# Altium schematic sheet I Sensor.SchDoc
size 431 x 279 mm; Date: Not shown in title block; ApprovedBy: Not shown in title block; CheckedBy: Not shown in title block; Author: Not shown in title block; CompanyName: Not shown in title block; DrawnBy: Forest Fu; Engineer: Not shown in title block; Organization: Not shown in title block; Address1: Not shown in title block; Address2: Not shown in title block; Address3: Not shown in title block; Address4: Not shown in title block; DocumentNumber: 1; Revision: Use project parameter SCH_Rev; SheetNumber: 5; SheetTotal: 6; PageSetup: Record=PageOptions¦CenterHorizontal=True¦CenterVertical=True¦PrintScale=1.00¦XCorrection=1.00¦YCorrection=1.00¦PrintKind=0¦BorderSize=5000000¦LeftOffset=0¦BottomOffset=0¦Orientation=2¦PaperLength=1000¦PaperWidth=1000¦Scale=100¦PaperSource=15¦PrintQuality=600¦MediaType=1¦DitherType=10¦PaperKind=Letter¦PrintScaleMode=1
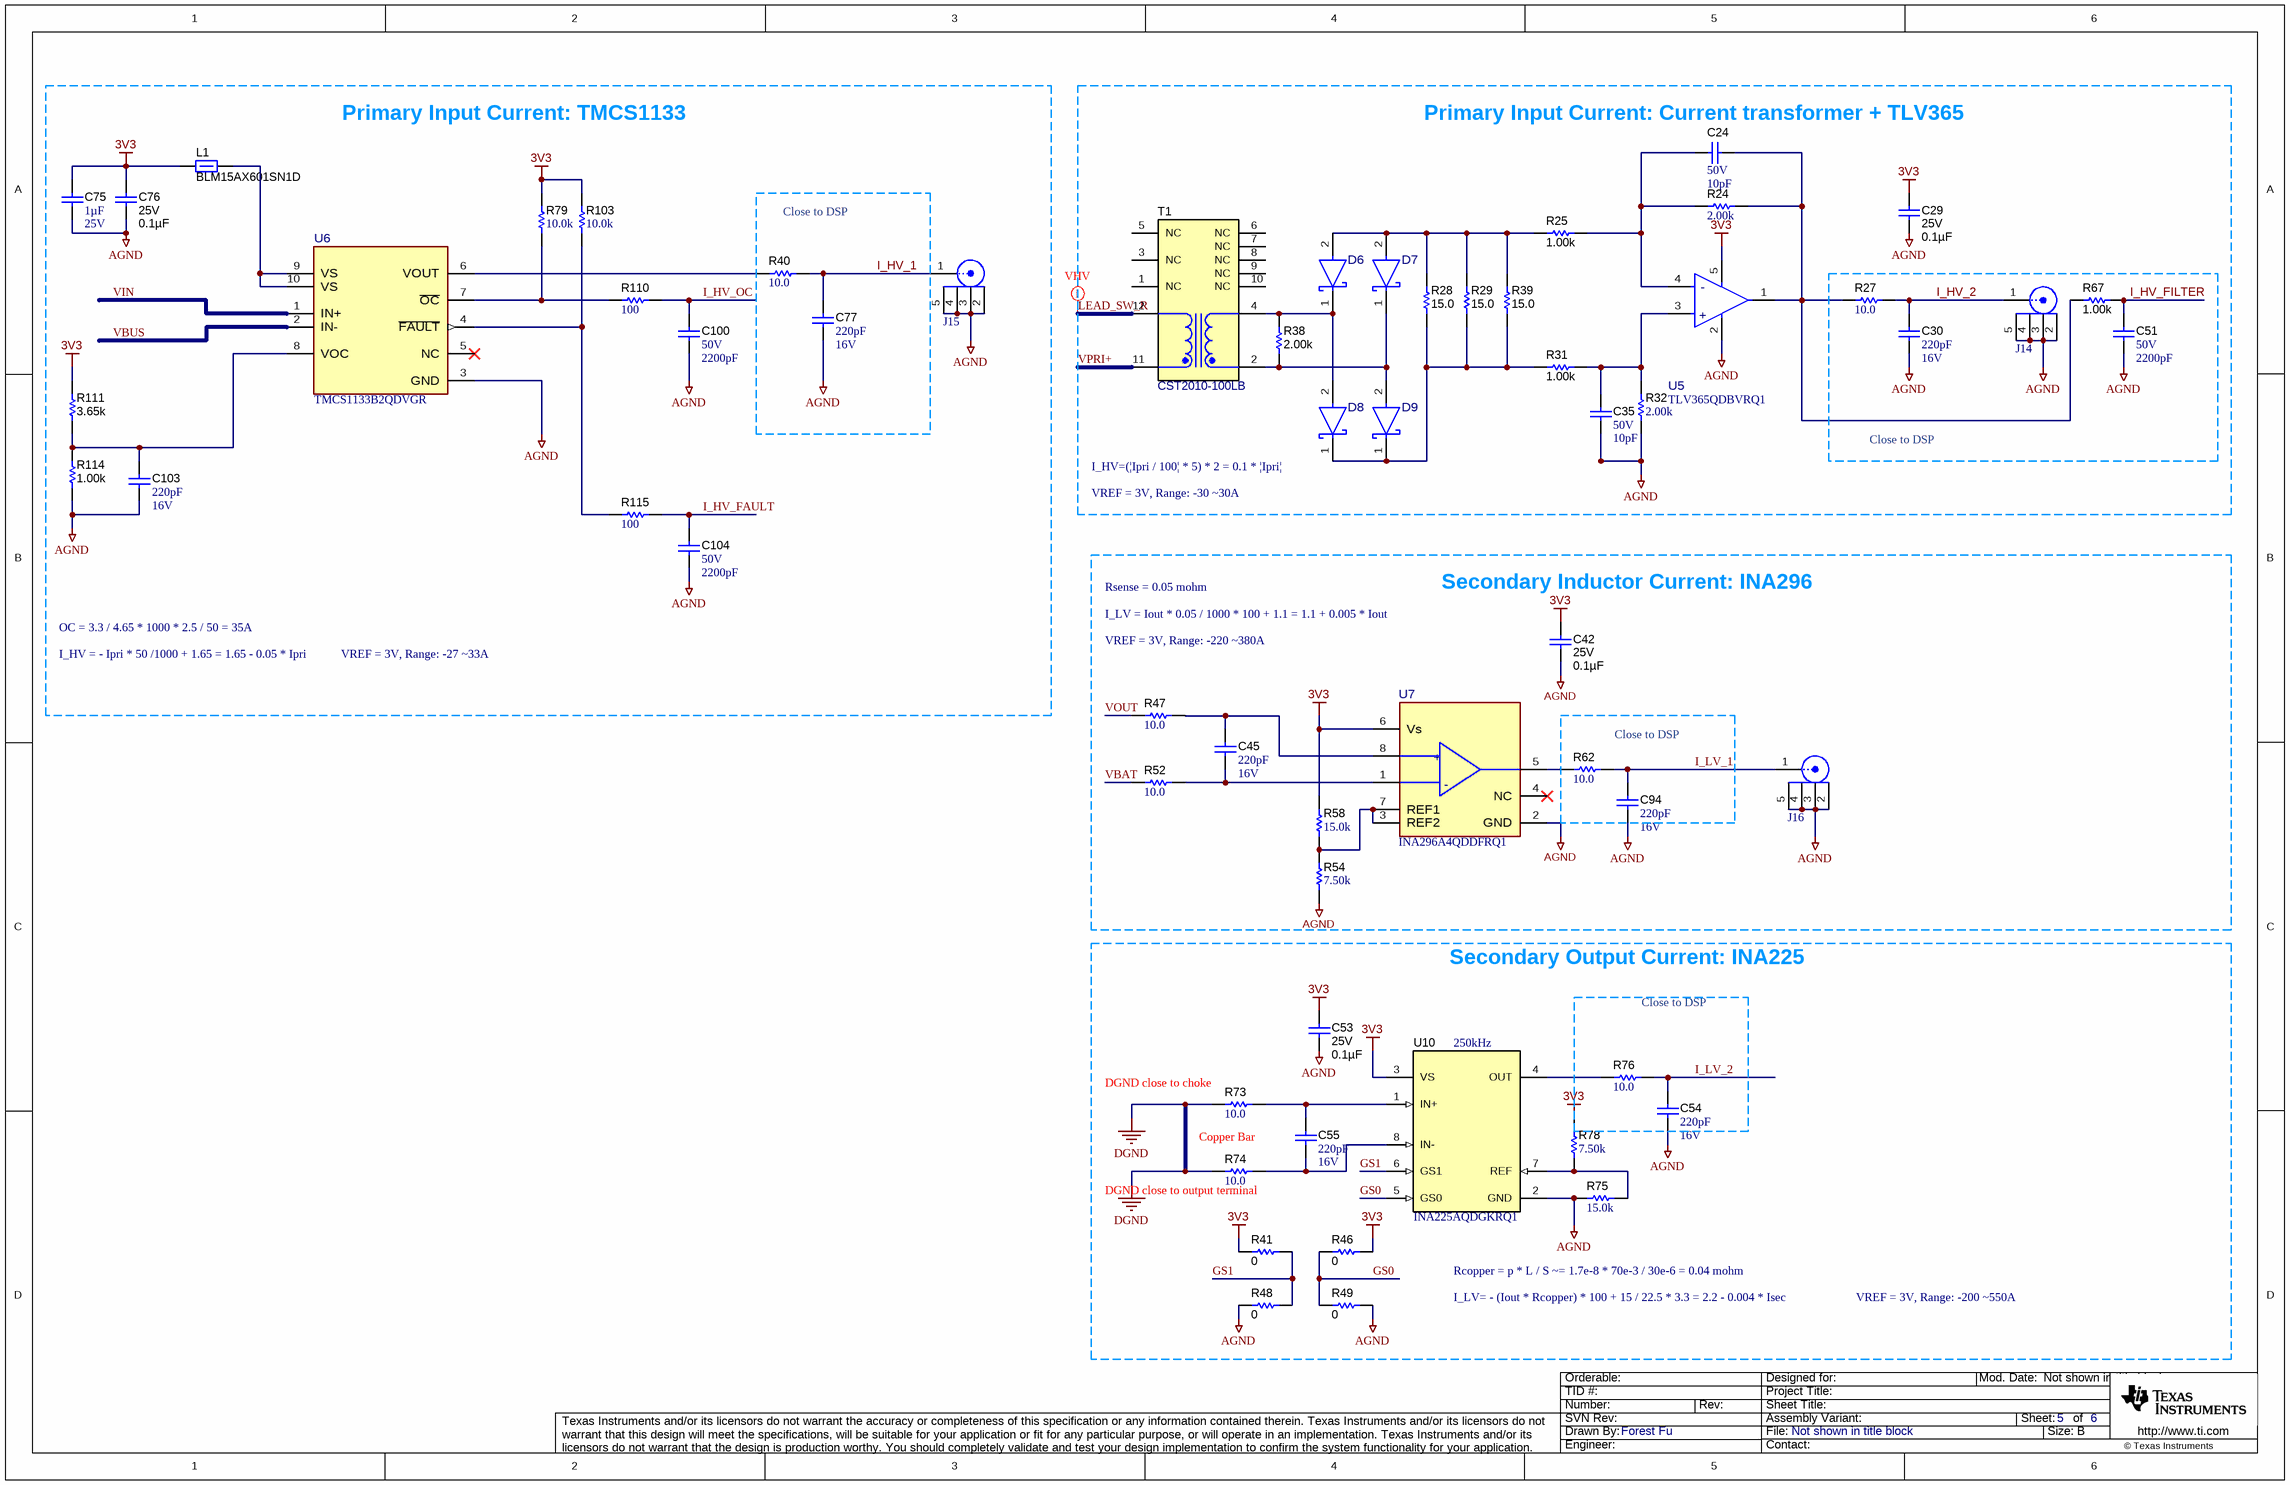
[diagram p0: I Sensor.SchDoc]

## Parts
C24  VDC_V: 50V  ValueDisplayed: 10pF  [0402]  (hidden comment: 04025U100CAT2A)
C29  VDC_V: 25V  ValueDisplayed: 0.1µF  [0402]  (hidden comment: CGA2B3X7R1E104K050BB)
C30  ValueDisplayed: 220pF  VDC_V: 16V  [0402]  (hidden comment: AC0402KRX7R7BB221)
C35  VDC_V: 50V  ValueDisplayed: 10pF  [0402]  (hidden comment: 04025U100CAT2A)
C42  VDC_V: 25V  ValueDisplayed: 0.1µF  [0402]  (hidden comment: CGA2B3X7R1E104K050BB)
C45  ValueDisplayed: 220pF  VDC_V: 16V  [0402]  (hidden comment: AC0402KRX7R7BB221)
C51  VDC_V: 50V  ValueDisplayed: 2200pF  [0402]  (hidden comment: GCM155R71H222KA37D)
C53  VDC_V: 25V  ValueDisplayed: 0.1µF  [0402]  (hidden comment: CGA2B3X7R1E104K050BB)
C54  ValueDisplayed: 220pF  VDC_V: 16V  [0402]  (hidden comment: AC0402KRX7R7BB221)
C55  ValueDisplayed: 220pF  VDC_V: 16V  [0402]  (hidden comment: AC0402KRX7R7BB221)
C75  Cap_F: 1µF  VDC_V: 25V  [0603S]  (hidden comment: CGA3E1X7R1E105K080AC)
C76  VDC_V: 25V  ValueDisplayed: 0.1µF  [0402]  (hidden comment: CGA2B3X7R1E104K050BB)
C77  ValueDisplayed: 220pF  VDC_V: 16V  [0402]  (hidden comment: AC0402KRX7R7BB221)
C94  ValueDisplayed: 220pF  VDC_V: 16V  [0402]  (hidden comment: AC0402KRX7R7BB221)
C100  VDC_V: 50V  ValueDisplayed: 2200pF  [0402]  (hidden comment: GCM155R71H222KA37D)
C103  ValueDisplayed: 220pF  VDC_V: 16V  [0402]  (hidden comment: AC0402KRX7R7BB221)
C104  VDC_V: 50V  ValueDisplayed: 2200pF  [0402]  (hidden comment: GCM155R71H222KA37D)
D6  MBR130T3G  [FP-MBR130T3G_SOD123-MFG]  (value not drawn)
D7  MBR130T3G  [FP-MBR130T3G_SOD123-MFG]  (value not drawn)
D8  MBR130T3G  [FP-MBR130T3G_SOD123-MFG]  (value not drawn)
D9  MBR130T3G  [FP-MBR130T3G_SOD123-MFG]  (value not drawn)
J14  0734151471  [Molex_0734151471]  (value not drawn)
J15  0734151471  [Molex_0734151471]  (value not drawn)
J16  0734151471  [Molex_0734151471]  (value not drawn)
L1  BLM15AX601SN1D  [0402]
R24  ValueDisplayed: 2.00k  [0402]  (hidden comment: ERJ-2RKF2001X)
R25  ValueDisplayed: 1.00k  [0402]  (hidden comment: CRCW04021K00FKED)
R27  ValueDisplayed: 10.0  [0402]  (hidden comment: RMCF0402JT10R0)
R28  ValueDisplayed: 15.0  [1206]  (hidden comment: CRCW120615R0FKEA)
R29  ValueDisplayed: 15.0  [1206]  (hidden comment: CRCW120615R0FKEA)
R31  ValueDisplayed: 1.00k  [0402]  (hidden comment: CRCW04021K00FKED)
R32  ValueDisplayed: 2.00k  [0402]  (hidden comment: ERJ-2RKF2001X)
R38  ValueDisplayed: 2.00k  [0603]  (hidden comment: CRCW06032K00FKEA)
R39  ValueDisplayed: 15.0  [1206]  (hidden comment: CRCW120615R0FKEA)
R40  ValueDisplayed: 10.0  [0402]  (hidden comment: RMCF0402JT10R0)
R41  ValueDisplayed: 0  [0402]  (hidden comment: CRCW04020000Z0ED)
R46  ValueDisplayed: 0  [0402]  (hidden comment: CRCW04020000Z0ED)
R47  ValueDisplayed: 10.0  [0402]  (hidden comment: RMCF0402JT10R0)
R48  ValueDisplayed: 0  [0402]  (hidden comment: CRCW04020000Z0ED)
R49  ValueDisplayed: 0  [0402]  (hidden comment: CRCW04020000Z0ED)
R52  ValueDisplayed: 10.0  [0402]  (hidden comment: RMCF0402JT10R0)
R54  ValueDisplayed: 7.50k  [0402]  (hidden comment: ERA-2AEB752X)
R58  ValueDisplayed: 15.0k  [0402]  (hidden comment: CRCW040215K0FKED)
R62  ValueDisplayed: 10.0  [0402]  (hidden comment: RMCF0402JT10R0)
R67  ValueDisplayed: 1.00k  [0402]  (hidden comment: CRCW04021K00FKED)
R73  ValueDisplayed: 10.0  [0402]  (hidden comment: RMCF0402JT10R0)
R74  ValueDisplayed: 10.0  [0402]  (hidden comment: RMCF0402JT10R0)
R75  ValueDisplayed: 15.0k  [0402]  (hidden comment: CRCW040215K0FKED)
R76  ValueDisplayed: 10.0  [0402]  (hidden comment: RMCF0402JT10R0)
R78  ValueDisplayed: 7.50k  [0402]  (hidden comment: ERA-2AEB752X)
R79  ValueDisplayed: 10.0k  [0402]  (hidden comment: RK73H1ETTP1002F)
R103  ValueDisplayed: 10.0k  [0402]  (hidden comment: RK73H1ETTP1002F)
R110  ValueDisplayed: 100  [0402]  (hidden comment: CRCW0402100RFKED)
R111  ValueDisplayed: 3.65k  [0402]  (hidden comment: CRCW04023K65FKED)
R114  ValueDisplayed: 1.00k  [0402]  (hidden comment: CRCW04021K00FKED)
R115  ValueDisplayed: 100  [0402]  (hidden comment: CRCW0402100RFKED)
T1  CST2010-100LB  [CST2010]
U5  TLV365QDBVRQ1  [DBV0005A-MFG]
U6  TMCS1133B2QDVGR  [DVG0010A-MFG]
U7  INA296A4QDDFRQ1  [DDF0008A-MFG]
U10  INA225AQDGKRQ1  [DGK0008A_N]

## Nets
3V3: C29.1 C42.1 C53.1 C75.1 C76.1 L1.1 R41.1 R46.1 R58.2 R78.2 R79.2 R103.2 R111.1 U5.5(V+) U7.6(Vs) U10.3(VS)
AGND: C29.2 C30.2 C35.2 C42.2 C51.2 C53.2 C54.2 C75.2 C76.2 C77.2 C94.2 C100.2 C103.2 C104.2 J14.2 J14.3 J14.4 J14.5 J15.2 J15.3 J15.4 J15.5 J16.2 J16.3 J16.4 J16.5 R32.1 R48.2 R49.1 R54.1 R75.1 R114.1 U5.2(V-) U6.3(GND) U7.2(GND) U10.2(GND)
DGND: R73.1 R74.1
GS0: R46.2 R49.2 U10.5(GS0)
GS1: R41.2 R48.1 U10.6(GS1)
I_HV_1: C77.1 J15.1 R40.2
I_HV_2: C30.1 J14.1 R27.2
I_HV_FAULT: C104.1 R115.2
I_HV_FILTER: C51.1 R67.2
I_HV_OC: C100.1 R110.2
I_LV_1: C94.1 J16.1 R62.2
I_LV_2: C54.1 R76.2
LEAD_SW_R: T1.12
VBAT: R52.1
VBUS: U6.2(IN-)
VIN: U6.1(IN+)
VOUT: R47.1
VPRI+: T1.11
NetC24_1: C24.1 R24.2 R27.1 R67.1 U5.1(VOUT)
NetC24_2: C24.2 R24.1 R25.2 U5.4(-IN)
NetC35_1: C35.1 R31.2 R32.2 U5.3(+IN)
NetC45_1: C45.1 R47.2 U7.8(IN+)
NetC45_2: C45.2 R52.2 U7.1(IN-)
NetC55_1: C55.1 R73.2 U10.1(IN+)
NetC55_2: C55.2 R74.2 U10.8(IN-)
NetC103_1: C103.1 R111.2 R114.2 U6.8(VOC)
NetD6_1: D6.1(CATHODE) D8.2(ANODE) R38.2 T1.4
NetD6_2: D6.2(ANODE) D7.2(ANODE) R25.1 R28.2 R29.2 R39.2
NetD7_1: D7.1(CATHODE) D9.2(ANODE) R38.1 T1.2
NetD8_1: D8.1(CATHODE) D9.1(CATHODE) R28.1 R29.1 R31.1 R39.1
NetL1_2: L1.2 U6.9(VS) U6.10(VS)
NetR40_1: R40.1 U6.6(VOUT)
NetR54_2: R54.2 R58.1 U7.3(REF2) U7.7(REF1)
NetR62_1: R62.1 U7.5(OUT)
NetR75_2: R75.2 R78.1 U10.7(REF)
NetR76_1: R76.1 U10.4(OUT)
NetR79_1: R79.1 R110.1 U6.7(~{OC})
NetR103_1: R103.1 R115.1 U6.4(~{FAULT})

Not connected (* = marked no-connect by the designer): T1 1(NC) 3(NC) 5(NC) 6(NC) 7(NC) 8(NC) 9(NC) 10(NC); U6 5(NC)*; U7 4(NC)*

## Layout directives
net class VHV: LEAD_SW_R

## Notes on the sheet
- Primary Input Current: TMCS1133
- (near C24) Primary Input Current: Current transformer + TLV365
- Close to DSP
- (near D8) I_HV=(¦Ipri / 100¦ * 5) * 2 = 0.1 * ¦Ipri¦
- VREF = 3V, Range: -30 ~30A
- OC = 3.3 / 4.65 * 1000 * 2.5 / 50 = 35A
- I_LV = Iout * 0.05 / 1000 * 100 + 1.1 = 1.1 + 0.005 * Iout
- Rsense = 0.05 mohm
- (near C42) Secondary Inductor Current: INA296
- I_HV = - Ipri * 50 /1000 + 1.65 = 1.65 - 0.05 * Ipri
- VREF = 3V, Range: -27 ~33A
- VREF = 3V, Range: -220 ~380A
- (near R62) Close to DSP
- Secondary Output Current: INA225
- (near R73) DGND close to choke
- (near U10) 250kHz
- Copper Bar
- (near R74) DGND close to output terminal
- I_LV= - (Iout * Rcopper) * 100 + 15 / 22.5 * 3.3 = 2.2 - 0.004 * Isec
- Rcopper = p * L / S ~= 1.7e-8 * 70e-3 / 30e-6 = 0.04 mohm
- VREF = 3V, Range: -200 ~550A

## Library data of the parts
C24 C35 = CMP-0064911-2: CAP, CERM, 10 pF, 50 V,+/- 2.5%, C0G/NP0, AEC-Q200 Grade 1, 0402; Manufacturer: AVX; TaMin_C: -55°C; Polarized: N; SizeAreaWB_mm2: 3; Value1: Unknown; U/M: EA; Value: 10pF; TaMax_C: 125°C; SizeZ_mm: 0.6; SizeX_mm: 1; SizeY_mm: 0.5; AEC Qualified: Y; AEC Category: Q200
C29 C42 C53 C76 = CMP-0080610-1: CAP, CERM, 0.1 µF, 25 V,+/- 10%, X7R, AEC-Q200 Grade 1, 0402; Manufacturer: TDK; TaMin_C: -55°C; Polarized: N; SizeAreaWB_mm2: 3; U/M: EA; Value: 0.1uF; TaMax_C: 125°C; SizeZ_mm: 0.6; SizeX_mm: 1; SizeY_mm: 0.5; AEC Qualified: Y; Cap_F: 100nF; AEC Category: Q200
C30 C45 C54 C55 C77 C94 C103 = CMP-0085176-1: CAP, CERM, 220 pF, 16 V,+/- 10%, X7R, AEC-Q200 Grade 1, 0402; Manufacturer: Yageo; Value: 220pF; SizeZ_mm: 0.6; TaMin_C: -55°C; AEC Category: Q200; AEC Qualified: Y; SizeY_mm: 0.5; SizeAreaWB_mm2: 3; AEC Grade: 1; U/M: EA; TaMax_C: 125°C; Polarized: N
C51 C100 C104 = CMP-0006357-2: CAP, CERM, 2200 pF, 50 V, +/- 10%, X7R, AEC-Q200 Grade 1, 0402; Manufacturer: MuRata; TaMin_C: -55°C; Polarized: N; SizeAreaWB_mm2: 3; Value1: Unknown; U/M: EA; Value: 2200pF; TaMax_C: 125°C; SizeZ_mm: 0.6; SizeX_mm: 1; SizeY_mm: 0.5; AEC Qualified: Y; Cap_F: 2.2nF; AEC Category: Q200
C75 = CMP-0076705-3: CAP, CERM, 1 µF, 25 V,+/- 10%, X7R, AEC-Q200 Grade 1, 0603; Manufacturer: TDK; SizeAreaWB_mm2: 4.68; SizeArea_mm2: 1.28; AEC Qualified: Y; AEC Category: Q200; Value: 1uF; TaMax_C: 125°C; SizeZ_mm: 1.0; AEC Grade: 1; Polarized: N; TaMin_C: -55°C; SizeY_mm: 0.8; U/M: EA; SizeX_mm: 1.6; Cap_Case: 1.6x0.8x0.8mm
D6-D9 = CMP-0094495-1: Diode Schottky 30 V 1A Surface Mount SOD-123; Manufacturer: onsemi; Import Ts: 1521868375; Standoff Height: 0mm; Vr_V: 30V; SizeZ_mm: 1.35mm; Peak Reverse Current: 60uA; TJmax_C: 125°C; Ciiva Ids: 822455; Max Surge Forward Current: 5.5A; AEC Qualified: No
J14-J16 = CMP-0055255-2: MMCX JACK, 50 Ohm, Gold, TH; Manufacturer: Molex; CT: FALSE; Gender: Female
L1 = CMP-0003317-1: Ferrite Bead, 600 ohm @ 100 MHz, 0.5 A, 0402; Manufacturer: MuRata; ZTyp@100MHz_Ohm: 600; SizeAreaWB_mm2: 3; DCR_ohm: 3.4d; Value1: 0.34 ohm; Value: 600 ohm; Imax_A: 5dA; SizeZ_mm: 0.6; SizeX_mm: 1; SizeY_mm: 0.5; Value2: 0.5A
R24 R32 = CMP-0026676-1: RES, 2.00 k, 1%, 0.1 W, AEC-Q200 Grade 0, 0402; Manufacturer: Panasonic; Power_W: 100mW; TempCo: 100 ppm/C; Value_Code: 2k00; U/M: EA; Value: 2.00k; EIA_Code: E96; Res_ohm: 2k; SizeX_mm: 1; SizeY_mm: 0.5; SizeZ_mm: 0.6; Value2: 0.1W; AEC Qualified: Y; VDC_V: 50V; AEC Grade: 0; AEC Category: Q200
R25 R31 R67 R114 = CMP-0026071-3: RES, 1.00 k, 1%, 0.063 W, AEC-Q200 Grade 0, 0402; Manufacturer: Vishay-Dale; Power_W: 63mW; TempCo: 100 ppm/C; Value_Code: 1k00; Value: 1.00k; EIA_Code: E96; Res_ohm: 1k; SizeX_mm: 1; SizeY_mm: 0.5; SizeZ_mm: 0.6; Value2: 0.063W; AEC Qualified: Y; VDC_V: 50V; AEC Category: Q200; AEC Grade: 0
R27 R40 R47 R52 R62 R73 R74 R76 = CMP-0026764-1: RES, 10.0, 1%, 0.063 W, AEC-Q200 Grade 0, 0402; Manufacturer: Stackpole Electronics Inc; Power_W: 63mW; TempCo: 100 ppm/C; Value_Code: 10R0; U/M: EA; Value: 10.0; EIA_Code: E96; Res_ohm: 10; SizeX_mm: 1; SizeY_mm: 0.5; SizeZ_mm: 0.6; Value2: 0.063W; AEC Qualified: Y; AEC Grade: 0; AEC Category: Q200
R28 R29 R39 = CMP-0016648-3: RES, 15.0, 1%, 0.25 W, AEC-Q200 Grade 0, 1206; Manufacturer: Vishay-Dale; Power_W: 250mW; TempCo: 100 ppm/C; Value_Code: 15R0; Value: 15.0; EIA_Code: E96; Res_ohm: 15; SizeX_mm: 3.2; SizeY_mm: 1.6; SizeZ_mm: 1.35; Value2: 0.25W; SizeArea_mm2: 5.12; AEC Qualified: Y; VDC_V: 200V; AEC Category: Q200; AEC Grade: 0
R38 = CMP-0022268-4: RES, 2.00 k, 1%, 0.1 W, AEC-Q200 Grade 0, 0603; Manufacturer: Vishay-Dale; Power_W: 100mW; TempCo: 100 ppm/C; Value_Code: 2k00; Value: 2.00k; EIA_Code: E96; Res_ohm: 2k; SizeX_mm: 1.6; SizeY_mm: 0.8; SizeZ_mm: 1; Value2: 0.1W; SizeArea_mm2: 1.28; AEC Qualified: Y; VDC_V: 75V; AEC Category: Q200; AEC Grade: 0
R41 R46 R48 R49 = CMP-0026822-3: RES, 0, 5%, 0.063 W, AEC-Q200 Grade 0, 0402; Manufacturer: Vishay-Dale; Power_W: 63mW; TempCo: 200 ppm/C; Value_Code: 0000; Value: 0; EIA_Code: E24; SizeX_mm: 1; SizeY_mm: 0.5; SizeZ_mm: 0.6; Value2: 0.063W; AEC Qualified: Y; VDC_V: 50V; AEC Category: Q200
R54 R78 = CMP-0026786-1: RES, 7.50 k, 0.1%, 0.063 W, AEC-Q200 Grade 0, 0402; Manufacturer: Panasonic; Power_W: 63mW; TempCo: 25 ppm/C; Value_Code: 7k50; U/M: EA; Value: 7.50k; EIA_Code: E192; Res_ohm: 7.5k; SizeX_mm: 1; SizeY_mm: 0.5; SizeZ_mm: 0.6; Value2: 0.063W; AEC Qualified: Y; VDC_V: 50V; AEC Grade: 0; AEC Category: Q200
R58 R75 = CMP-0026027-3: RES, 15.0 k, 1%, 0.063 W, AEC-Q200 Grade 0, 0402; Manufacturer: Vishay-Dale; Power_W: 63mW; TempCo: 100 ppm/C; Value_Code: 15k0; Value: 15.0k; EIA_Code: E96; Res_ohm: 15k; SizeX_mm: 1; SizeY_mm: 0.5; SizeZ_mm: 0.6; Value2: 0.063W; AEC Qualified: Y; VDC_V: 50V; AEC Category: Q200; AEC Grade: 0
R79 R103 = CMP-0026748-1: RES, 10.0 k, 1%, 0.063 W, AEC-Q200 Grade 0, 0402; Manufacturer: KOA Speer; Power_W: 63mW; TempCo: 100 ppm/C; Value_Code: 10k0; U/M: EA; Value: 10.0k; EIA_Code: E96; Res_ohm: 10k; SizeX_mm: 1; SizeY_mm: 0.5; SizeZ_mm: 0.6; Value2: 0.063W; AEC Qualified: Y; VDC_V: 50V; AEC Grade: 0; AEC Category: Q200
R110 R115 = CMP-0025951-3: RES, 100, 1%, 0.063 W, AEC-Q200 Grade 0, 0402; Manufacturer: Vishay-Dale; Power_W: 63mW; TempCo: 100 ppm/C; Value_Code: 100R; Value: 100; EIA_Code: E96; SizeX_mm: 1; SizeY_mm: 0.5; SizeZ_mm: 0.6; Value2: 0.063W; AEC Qualified: Y; VDC_V: 50V; AEC Category: Q200; AEC Grade: 0
R111 = CMP-0026337-2: RES, 3.65 k, 1%, 0.063 W, AEC-Q200 Grade 0, 0402; Manufacturer: Vishay-Dale; Power_W: 63mW; TempCo: 100 ppm/C; Value_Code: 3k65; Value: 3.65k; EIA_Code: E96; SizeX_mm: 1; SizeY_mm: 0.5; SizeZ_mm: 0.6; Value2: 0.063W; AEC Qualified: Y; VDC_V: 50V; AEC Category: Q200; AEC Grade: 0
T1 = CMP-0085494-1: Current Sense Transformer, 8.5 mH, 254 Vµs, 40 A, AEC-Q200 Grade 1, SMT; Manufacturer: Coilcraft; SizeArea_mm2: 289.6905; Lp: 8500; SizeX_mm: 19.91; Ns1toNp: 100; SizeY_mm: 14.55; SizeAreaWB_mm2: 362.6105; AEC Grade: 1; Value: 8.5mH; Rsec1_ohm: 1.45; SizeZ_mm: 10.5; DCR_ohm: 360µ; AEC Category: Q200; AEC Qualified: Y
U5 = CMP-0121215-2: Automotive 50-MHz single-supply operational amplifier with rail-to-rail input and output 5-SOT-23 -40 to 125; Manufacturer: Texas Instruments; SizeZ_mm: 1.45mm; AEC Qualified: Yes; AEC Grade: Grade 1; Gain Bandwidth: 50MHz; Input Bias Current: 0.000005uA; Input Offset Voltage: 0.4mV; Max Supply Voltage: 5.5V; Min Supply Voltage: 2.2V; Nominal Supply Current: 4.6mA; Number Of Channels: 1; Output Current Per Channel: 85mA; Response Time: 0.2us; Standoff Height: 0mm; TaMax_C: +125°C; TaMin_C: -40°C; TJmax_C: +150°C; Voltage Gain: 120dB; AEC Category: Q200; CompType: IC
U6 = CMP-0097985-1: Manufacturer: Texas Instruments; SizeZ_mm: 2.65mm; Standoff Height: 0.1mm
U7 = CMP-0121413-1: AEC-Q100, -5-V to 110-V, bidirectional, 1.1-MHz 8-V/µs ultraprecise current sense amplifier; Manufacturer: Texas Instruments; SizeZ_mm: 1.1mm; AEC Qualified: Yes; AEC Grade: Grade 1; Bandwidth: 1.1MHz; Input Bias Current: 35uA; Input Offset Voltage: 0.003mV; Max Supply Voltage: 20V; Min Supply Voltage: 2.7V; Nominal Supply Current: 2.5mA; Number Of Channels: 1; Response Time: 1.5us; Standoff Height: 0mm; TaMax_C: +125°C; TaMin_C: -40°C; TJmax_C: +150°C; Voltage Gain: 0.1V/mV
U10 = CMP-0065433-2: Automotive, 36-V Prog. Gain, Bi-Directional, Zero-Drift, High-Speed Voltage Out Current Sense Amp, DGK0008A (VSSOP-8); Alternate Manufacturer: Texas Instruments; SizeAreaWB_mm2: 23.6; SizeZ_mm: 1.1; SizeX_mm: 4.9; SizeY_mm: 3; SizeArea_mm2: 14.7; CompType: IC; AEC Category: Q200; AEC Qualified: Y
